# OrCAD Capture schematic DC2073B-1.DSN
size Custom; title: RESISTOR - SET OSCILLATOR IC; rev: 1; company: TM
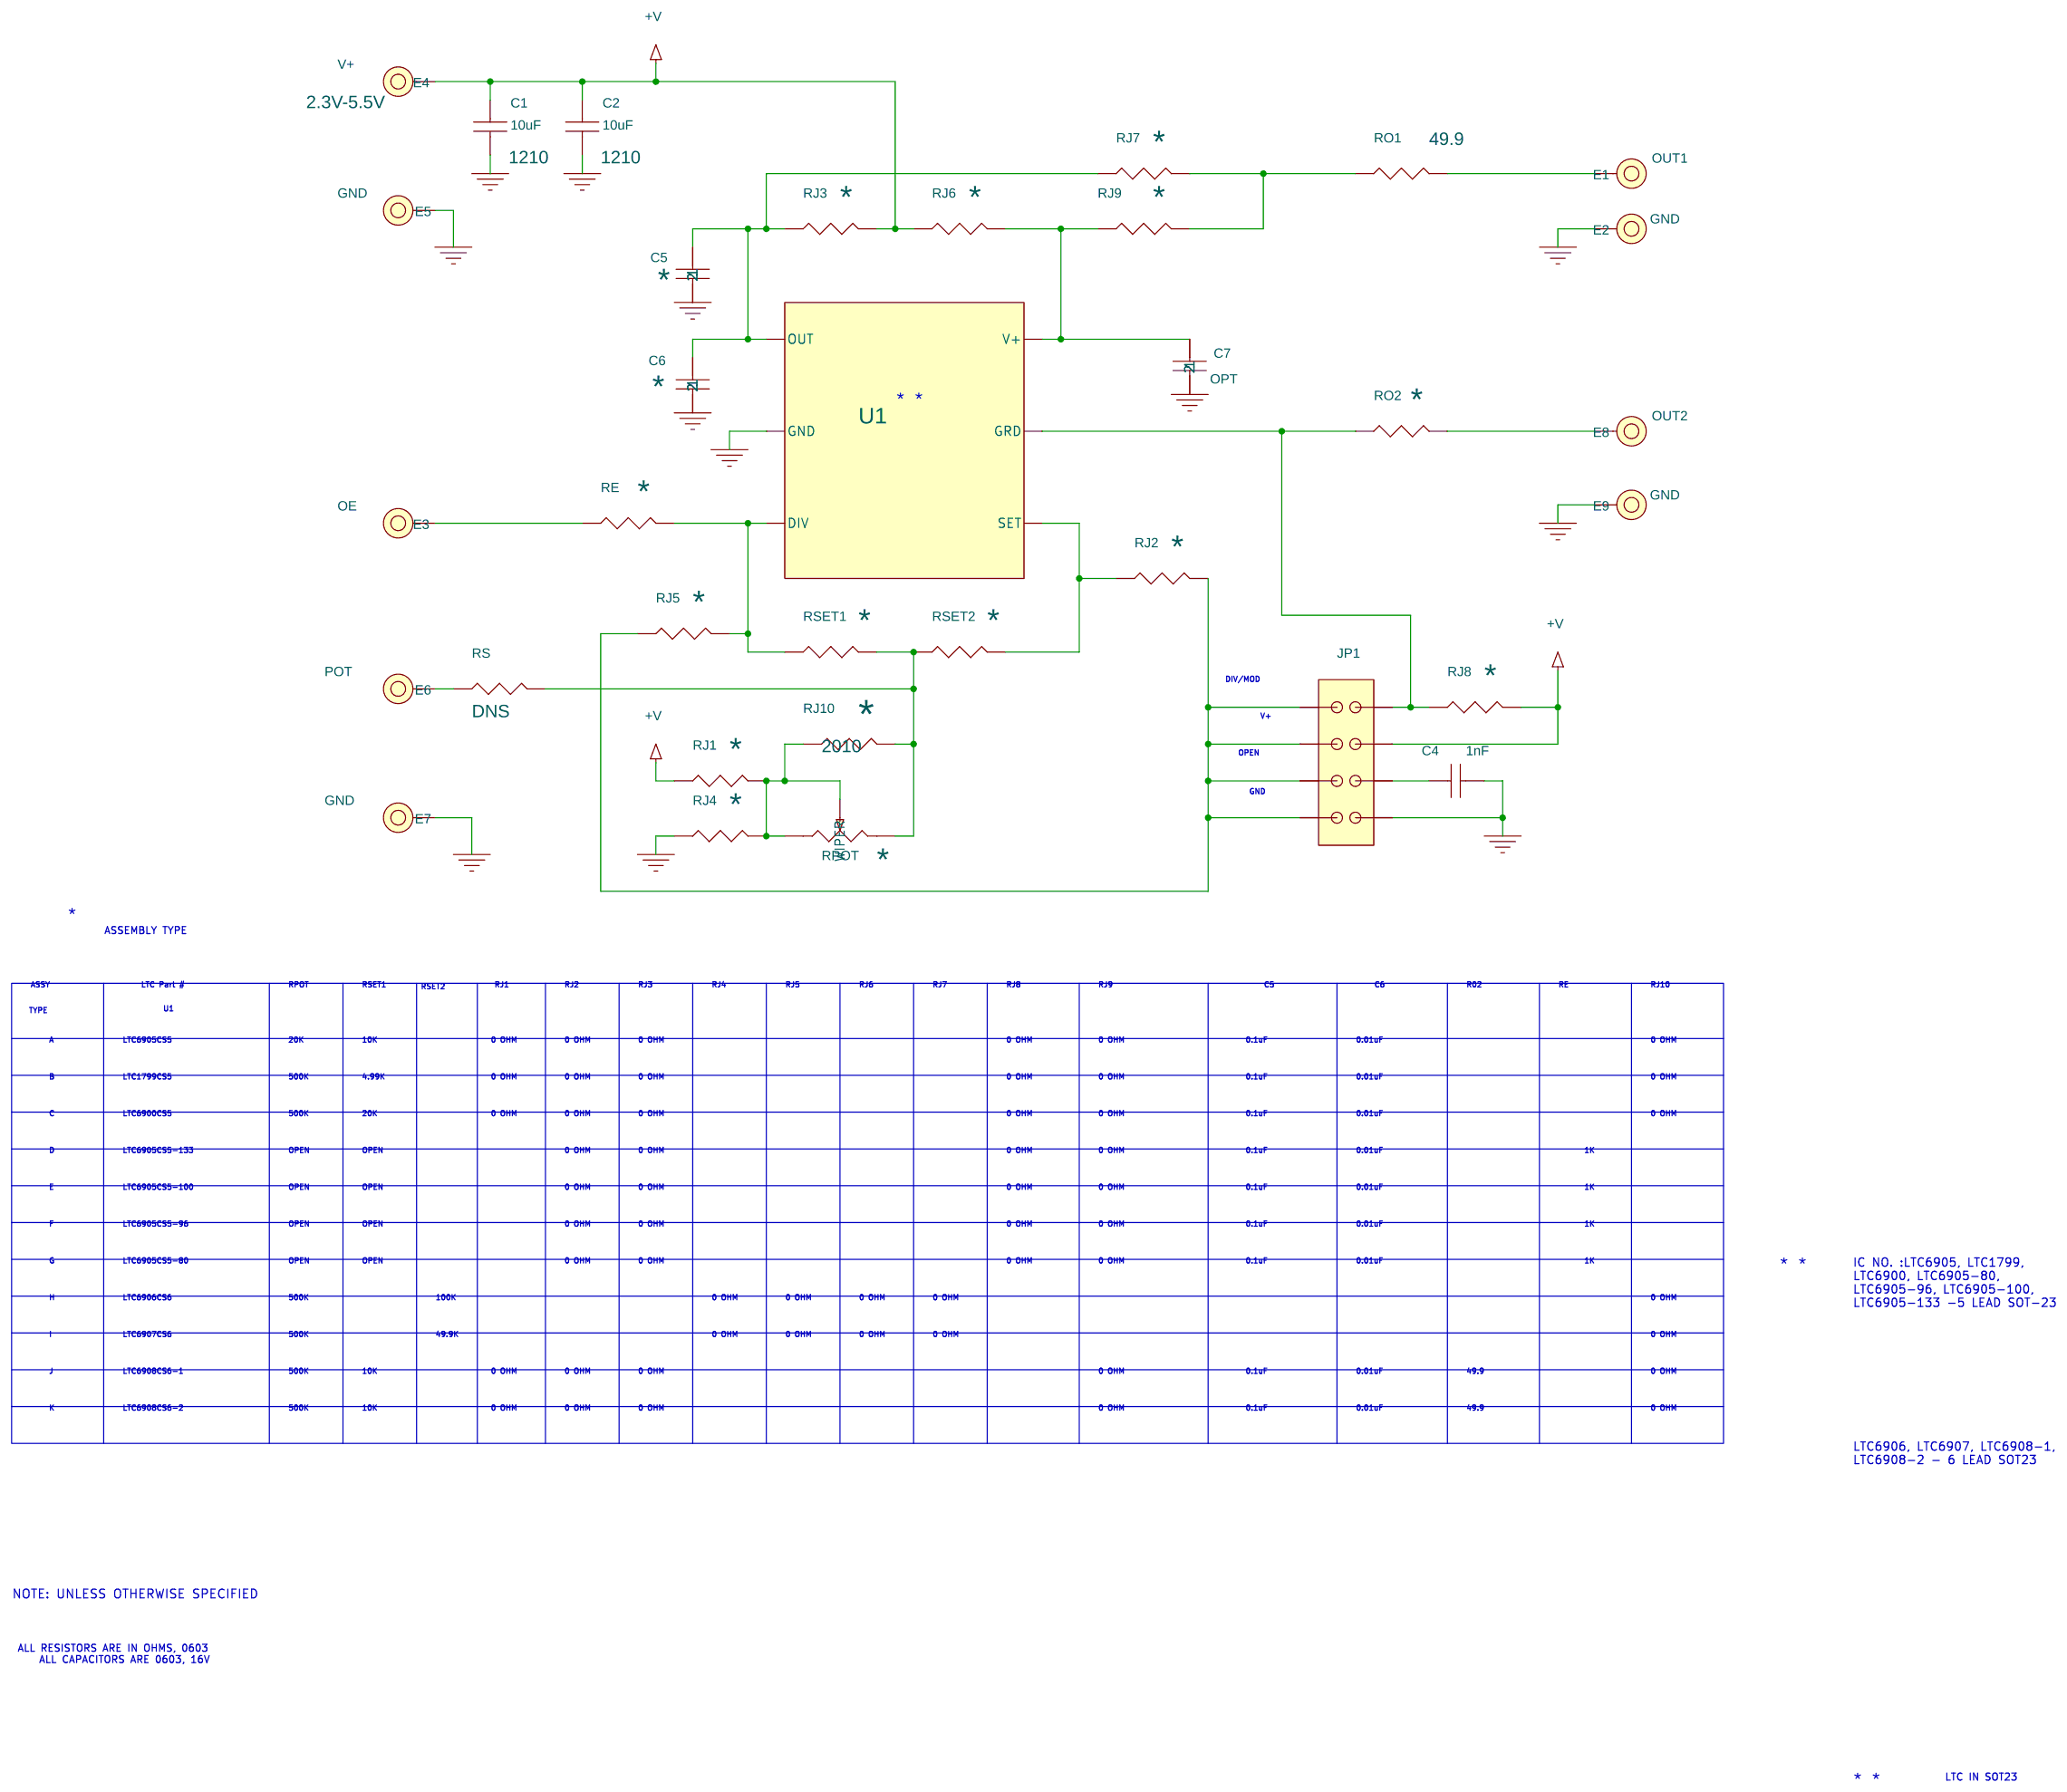
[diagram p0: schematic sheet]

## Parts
C1  10uF  [1210]
C2  10uF  [1210]
C4  1nF  [0603]
C5  *  [0603]
C6  *  [0603]
C7  OPT  [0603]
E1  OUT1  [MM/2308]
E2  GND  [MM/2308]
E3  OE  [MM/2308]
E4  V+  [MM/2308]
E5  GND  [MM/2308]
E6  POT  [MM/2308]
E7  GND  [MM/2308]
E8  OUT2  [MM/2308]
E9  GND  [MM/2308]
JP1  Double 8-position 1mm  [HEADER-2X4-2MM]
RE  *  [0603]
RJ1  *  [0603]
RJ2  *  [0603]
RJ3  *  [0603]
RJ4  *  [0603]
RJ5  *  [0603]
RJ6  *  [0603]
RJ7  *  [0603]
RJ8  *  [0603]
RJ9  *  [0603]
RJ10  *  [2010]
RO1  49.9  [0603]
RO2  *  [0603]
RPOT  *  [POT-TH-T93YA-VISHAY]
RS  DNS  [0603]
RSET1  *  [0603]
RSET2  *  [0603]
U1  Low Pwr. Resistor Set Osc.  [TSOT-23-6]
XJP1  2mm Ctrs.

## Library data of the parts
C1 = 08053C104KAT2A_1: 4th Part Field: Vishay; 5th Part Field: VJ0805Y104KXAAT
C2 = 08053C104KAT2A: 4th Part Field: Vishay; 5th Part Field: VJ0805Y104KXAAT
C4 = 08053C104KAT2A_2: 4th Part Field: Vishay; 5th Part Field: VJ0805Y104KXAAT
C5 = 08055C102KAT1A: 1st Part Field: 25V; 3rd Part Field: NPO; 5th Part Field: 08053A102KAT2A; 7th Part Field: Cap.,
C6 = 08055C102KAT1A_2: 1st Part Field: 25V; 3rd Part Field: NPO; 5th Part Field: 08053A102KAT2A; 7th Part Field: Cap.,
C7 = 08055C102KAT1A_1: 1st Part Field: 25V; 3rd Part Field: NPO; 5th Part Field: 08053A102KAT2A; 7th Part Field: Cap.,
E1 E2 E5-E9 = CON_KEY_575-4_0
E3 E4 = CON_KEY_575-4_0: 4th Part Field: 2.3V-5.5V
JP1 = Commcon2202s08g2: 5th Part Field: 6251-08G1
RE RJ1-RJ10 RO2 RSET1 RSET2 = CRCW0805604RFKTA: 1st Part Field: 1/4W; 5th Part Field: CRCW08051003F
RO1 = CRCW0805604RFKTA: 1st Part Field: 1/4W; 5th Part Field: CRCW08051003F; 9th Part Field: 10
RPOT = 100_OHM_TRIMPOT,_CERMET
RS = CRCW0805604RFKTA: 1st Part Field: 1/4W; 5th Part Field: CRCW08051003F; 9th Part Field: OPT
U1 = LTC6908?DCB-?_6: 5th Part Field: *
XJP1 = CommconCCIJ2MM-138G_0

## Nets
GND: C1.2 C2.2 C4.2 C5.2 C6.2 C7.2 E2.1 E5.1 E7.1 E9.1 JP1.8 RJ4.1 U1.2(GND)
+V: C1.1 C2.1 E4.1 JP1.4 RJ1.1 RJ3.2 RJ6.1 RJ8.2
N16720802: C5.1 C6.1 RJ3.1 RJ7.1 U1.1(OUT)
N16724615: C7.1 RJ6.2 RJ9.1 U1.6(V+)
N16730385: RE.2 RJ5.2 RSET1.1 U1.3(DIV)
N16730792: E3.1 RE.1
N16731136: RJ2.1 RSET2.2 U1.4(SET)
N16734853: E6.1 RS.1
N16734963: RJ10.2 RPOT.3 RS.2 RSET1.2 RSET2.1
N16737042: RJ1.2 RJ4.2 RJ10.1 RPOT.1 RPOT.2(WIPER)
N16744978: JP1.1 JP1.3 JP1.5 JP1.7 RJ2.2 RJ5.1
N16751591: JP1.2 RJ8.1 RO2.1 U1.5(GRD)
N16752491: C4.1 JP1.6
N16763271: E8.1 RO2.2
N16765106: RJ7.2 RJ9.2 RO1.1
N16770692: E1.1 RO1.2

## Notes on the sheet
- *
- *
- DIV/MOD
- V+
- OPEN
- GND
- *
- ASSEMBLY TYPE
- ASSY
- LTC Part #
- RPOT
- RSET1
- RSET2
- RJ1
- RJ2
- RJ3
- RJ4
- RJ5
- RJ6
- RJ7
- RJ8
- RJ9
- C5
- C6
- R02
- RE
- RJ10
- TYPE
- U1
- A
- LTC6905CS5
- 20K
- 10K
- 0 OHM
- 0 OHM
- 0 OHM
- 0 OHM
- 0 OHM
- 0.1uF
- 0.01uF
- 0 OHM
- B
- LTC1799CS5
- 500K
- 4.99K
- 0 OHM
- 0 OHM
- 0 OHM
- 0 OHM
- 0 OHM
- 0.1uF
- 0.01uF
- 0 OHM
- C
- LTC6900CS5
- 500K
- 20K
- 0 OHM
- 0 OHM
- 0 OHM
- 0 OHM
- 0 OHM
- 0.1uF
- 0.01uF
- 0 OHM
- D
- LTC6905CS5-133
- OPEN
- OPEN
- 0 OHM
- 0 OHM
- 0 OHM
- 0 OHM
- 0.1uF
- 0.01uF
- 1K
- E
- LTC6905CS5-100
- OPEN
- OPEN
- 0 OHM
- 0 OHM
- 0 OHM
- 0 OHM
- 0.1uF
- 0.01uF
- 1K
- F
- LTC6905CS5-96
- OPEN
- OPEN
- 0 OHM
- 0 OHM
- 0 OHM
- 0 OHM
- 0.1uF
- 0.01uF
- 1K
- G
- LTC6905CS5-80
- OPEN
- OPEN
- 0 OHM
- 0 OHM
- 0 OHM
- 0 OHM
- 0.1uF
- 0.01uF
- 1K
- *
- *
- IC NO. :LTC6905, LTC1799,
  LTC6900, LTC6905-80,
  LTC6905-96, LTC6905-100,
  LTC6905-133 -5 LEAD SOT-23
- H
- LTC6906CS6
- 500K
- 100K
- 0 OHM
- 0 OHM
- 0 OHM
- 0 OHM
- 0 OHM
- I
- LTC6907CS6
- 500K
- 49.9K
- 0 OHM
- 0 OHM
- 0 OHM
- 0 OHM
- 0 OHM
- J
- LTC6908CS6-1
- 500K
- 10K
- 0 OHM
- 0 OHM
- 0 OHM
- 0 OHM
- 0.1uF
- 0.01uF
- 49.9
- 0 OHM
- K
- LTC6908CS6-2
- 500K
- 10K
- 0 OHM
- 0 OHM
- 0 OHM
- 0 OHM
- 0.1uF
- 0.01uF
- 49.9
- 0 OHM
- LTC6906, LTC6907, LTC6908-1,
  LTC6908-2 - 6 LEAD SOT23
- NOTE: UNLESS OTHERWISE SPECIFIED
- ALL RESISTORS ARE IN OHMS, 0603
       ALL CAPACITORS ARE 0603, 16V
- *
- *
- LTC IN SOT23
